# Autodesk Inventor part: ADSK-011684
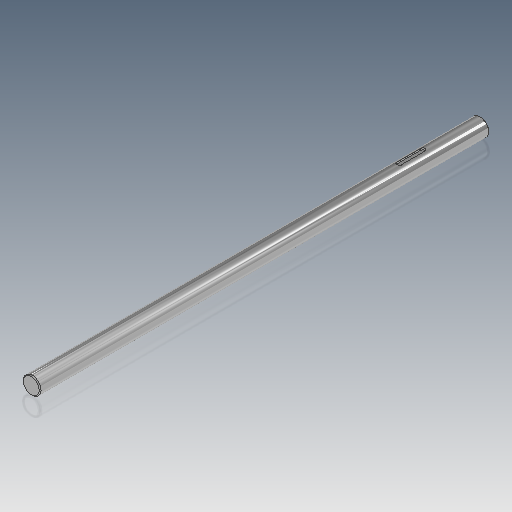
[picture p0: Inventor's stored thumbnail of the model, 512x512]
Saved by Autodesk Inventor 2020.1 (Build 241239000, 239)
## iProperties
Created: 1999-12
Part Number: ADSK-011684
Material: Acier doux
Description: SHFT-T,TH,FX,07-06,200,LH
Document SubType Name: Modeling
Designer: sspink
Density: 7.86 g/cm^3
Appearance: Chrom - poliert
Mass: 1251.61 g
Surface Area: 325.89 cm^2
Volume: 159.239 cm^3
Control State: 0
Master: False
Checked Out: False
Shininess: 0.0
Length Units: 11269
Angle Units: 11279
Time Units: 11290
Mass Units: 11283
Length Display Precision: 3
Angle Display Precision: 2
Compacted: True
CUTLENGTH: 20
MATERIAL DESC: THREADED-ROD,0.75-06 ACME LH
MATERIAL_NUMBER: A084662
Dimensions: 20x20x508 mm
Mass: 1,252 kg
DocNumber: ADSK-011684.ipt
Folder: 01 - Themengebiete\Simplification\01 - Packaging machine\
VDS_Category: 3D Komponenten
Density: 0.0
Volumn: 0.0
Area: 0.0
PropertySet Name: Model Information
Author: sspink
Revision Number: -
Title: shaft
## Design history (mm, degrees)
node "Solide1"
  node "Extrusion1" dims "d1" = 508, "d2" = 0
  node "Extrusion3" dims "d9" = 32, "d10" = 0
sketch "Sketch1"
  geometry: C1 r 10 at (0, 0); 1 further point
  constraints: 1 centre point, 1 coincident
  dimensions: "d0" = 20 diameter of C1
workplane "Work Plane1"
sketch "Sketch3"
  geometry: L1 (2.5, 9.682)-(2.5, 8); L2 (2.5, 8)-(-2.5, 8); L3 (-2.5, 8)-(-2.5, 9.682); A1 r 10 centre (0, 0) between (2.5, 9.682) and (-2.5, 9.682) reference; A2 r 10 centre (0, 0) between (2.5, 9.682) and (-2.5, 9.682); 1 further point
  constraints: 6 end point, 4 point on circle, 2 concentric, 2 perpendicular, 1 centre point, 1 midpoint, 1 vertical, 1 vertical alignment
  dimensions: "d14" = 5 distance of L1.end L2.end; "d15" = 2 distance edge to line of A1 L2
chamfer "Fase1" distance "d11" = 1; stored, may be unused: second distance "d12" = 2, angle "d13" = 45 deg
fillet "Rundung1"
fillet "Rundung2"
node "Corps solides"
node "Corps surfaciques"
other parameters: "d8" = -63
